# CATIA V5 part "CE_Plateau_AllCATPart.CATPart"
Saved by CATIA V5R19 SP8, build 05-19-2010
Part number: CE3_Plateau_AllCATPart
Bounding box of the stored display mesh (mm): x -297.501 to 295.5, y 20.663 to 1583.163, z -37.994 to 169.547
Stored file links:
  D:\Documents\1_Travail\1 - ac-limoges.fr\ac-limoges.fr\Emmanuel Maynard - STI2D_Turgot\2 -2I2D\1_SEQUENCE_ Tapis_de_course\3- Spécificités\Spé_ITEC\3-Pente\Tapis_TC520B_Pente\CE_Plateau_AllCATPart.CATPart
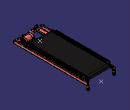
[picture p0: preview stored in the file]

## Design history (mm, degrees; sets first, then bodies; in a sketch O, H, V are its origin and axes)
AxisSystem1: origin (0, 0, 0), X (1, 0, 0), Y (0, 1, 0), Z (0, 0, 1)
Body1 (main body)
  Sketch1 on YZ plane of AxisSystem1, origin (0, 0, 0), H (0, 1, 0), V (0, 0, 1)
    projected circle E1 centre (1555.6634, -10.5) radius 27.5 from edge [face of Solid100 | face of Solid100]
  Sketch2 on yz-plane, origin (0, 0, 0), H (0, 1, 0), V (0, 0, 1)
    point P1 (1555.6634, -10.5)
    reference projected point E1 (1555.6634, -10.5) from axis of face of Solid100
    projected point E2 (98.6634, 148.5) from axis of face of Solid102
    projected point E3 (280.6634, 75.5) from axis of face of Solid103
    coincidence: P1 E1
  Body2 "S/S Roulettes.1\\Vis ISO 7380 Tete bombee a six pans creux M8x40.1"
    Solid1: solid without history
    Body3 "S/S Roulettes.1\\Vis ISO 7380 Tete bombee a six pans creux M8x40.1\\Corps de pièce.2"
      Solid2 "Solide.1": solid without history
    Add1 "S/S Roulettes.1\\Vis ISO 7380 Tete bombee a six pans creux M8x40.1\\Corps de pièce.2": tool Body3
  Add2: tool Body2
  Body4 "S/S Roulettes.1\\ecrou_iso_7040-M8-10.1\\ecrou_iso_7040-m8-10"
    Solid3 "Solide.1": solid without history
  Add3: tool Body4
  Body5 "S/S Roulettes.1\\Vis ISO 7380 Tete bombee a six pans creux M8x40.2"
    Solid4 "Solide.1": solid without history
    Body6 "S/S Roulettes.1\\Vis ISO 7380 Tete bombee a six pans creux M8x40.2\\Corps de pièce.2"
      Solid5 "Solide.1": solid without history
    Add4 "S/S Roulettes.1\\Vis ISO 7380 Tete bombee a six pans creux M8x40.2\\Corps de pièce.2": tool Body6
  Add5: tool Body5
  Body7 "S/S Roulettes.1\\ecrou_iso_7040-M8-10.2\\ecrou_iso_7040-m8-10"
    Solid6 "Solide.1": solid without history
  Add6: tool Body7
  Body8 "S/S Roulettes.1\\Part1.8\\Corps principal"
    Solid7 "Solide.1": solid without history
  Add7: tool Body8
  Body9 "s/s Moteur.1\\ISO 4762 SCREW M8x16 STEEL HEXAGON SOCKET HEAD CAP.4\\PartBody"
    Solid8 "Solide.1": solid without history
  Add8: tool Body9
  Body10 "s/s Moteur.1\\ISO 8738 WASHER 8 STEEL GRADE A PLAIN WASHER FOR CLEVIS PIN.6\\Corps principal"
    Solid9 "Solide.1": solid without history
  Add9: tool Body10
  Body11 "s/s Moteur.1\\ISO 4762 SCREW M8x16 STEEL HEXAGON SOCKET HEAD CAP.3\\PartBody"
    Solid10 "Solide.1": solid without history
  Add10: tool Body11
  Body12 "s/s Moteur.1\\ronw8a2.6\\ronw8a2"
    Solid11 "Solide.1": solid without history
  Add11: tool Body12
  Body13 "s/s Moteur.1\\ronw8a2.5\\ronw8a2"
    Solid12 "Solide.1": solid without history
  Add12: tool Body13
  Body14 "s/s Moteur.1\\ISO 8738 WASHER 8 STEEL GRADE A PLAIN WASHER FOR CLEVIS PIN.5\\Corps principal"
    Solid13 "Solide.1": solid without history
  Add13: tool Body14
  Body15 "s/s Moteur.1\\ISO 4016 BOLT M8x40 STEEL GRADE C HEXAGON HEAD.1\\PartBody"
    Solid14 "Solide.1": solid without history
  Add14: tool Body15
  Body16 "s/s Moteur.1\\ISO 4032 NUT M8 STEEL GRADE A HEXAGON.1\\Corps principal"
    Solid15 "Solide.1": solid without history
  Add15: tool Body16
  Body17 "s/s Moteur.1\\Part1.13\\Corps principal"
    Solid16 "Solide.1": solid without history
  Add16: tool Body17
  Body18 "s/s Moteur.1\\ISO 4762 SCREW M8x16 STEEL HEXAGON SOCKET HEAD CAP.2\\PartBody"
    Solid17 "Solide.1": solid without history
  Add17: tool Body18
  Body19 "s/s Moteur.1\\ISO 4762 SCREW M8x35 STEEL HEXAGON SOCKET HEAD CAP.2\\PartBody"
    Solid18 "Solide.1": solid without history
  Add18: tool Body19
  Body20 "s/s Moteur.1\\ISO 4762 SCREW M8x35 STEEL HEXAGON SOCKET HEAD CAP.1\\PartBody"
    Solid19 "Solide.1": solid without history
  Add19: tool Body20
  Body21 "s/s Moteur.1\\ISO 4762 SCREW M8x16 STEEL HEXAGON SOCKET HEAD CAP.1\\PartBody"
    Solid20 "Solide.1": solid without history
  Add20: tool Body21
  Body22 "s/s Moteur.1\\ronw8a2.4\\ronw8a2"
    Solid21 "Solide.1": solid without history
  Add21: tool Body22
  Body23 "s/s Moteur.1\\ronw8a2.3\\ronw8a2"
    Solid22 "Solide.1": solid without history
  Add22: tool Body23
  Body24 "s/s Moteur.1\\ronw8a2.2\\ronw8a2"
    Solid23 "Solide.1": solid without history
  Add23: tool Body24
  Body25 "s/s Moteur.1\\ronw8a2.1\\ronw8a2"
    Solid24 "Solide.1": solid without history
  Add24: tool Body25
  Body26 "s/s Moteur.1\\ISO 8738 WASHER 8 STEEL GRADE A PLAIN WASHER FOR CLEVIS PIN.4\\Corps principal"
    Solid25 "Solide.1": solid without history
  Add25: tool Body26
  Body27 "s/s Moteur.1\\ISO 8738 WASHER 8 STEEL GRADE A PLAIN WASHER FOR CLEVIS PIN.3\\Corps principal"
    Solid26 "Solide.1": solid without history
  Add26: tool Body27
  Body28 "s/s Moteur.1\\ISO 8738 WASHER 8 STEEL GRADE A PLAIN WASHER FOR CLEVIS PIN.2\\Corps principal"
    Solid27 "Solide.1": solid without history
  Add27: tool Body28
  Body29 "s/s Moteur.1\\ISO 8738 WASHER 8 STEEL GRADE A PLAIN WASHER FOR CLEVIS PIN.1\\Corps principal"
    Solid28 "Solide.1": solid without history
  Add28: tool Body29
  Body30 "s/s Moteur.1\\Part1.12\\Corps principal"
    Solid29 "Solide.1": solid without history
  Add29: tool Body30
  Body31 "s/s plaque.1\\Part1.2"
    Solid30 "Solide.1": solid without history
    Body32 "s/s plaque.1\\Part1.2\\Vis"
      Solid31 "Solide.1": solid without history
    Add30 "s/s plaque.1\\Part1.2\\Vis": tool Body32
    Body33 "s/s plaque.1\\Part1.2\\Corps de pièce.5"
      Solid32 "Solide.1": solid without history
    Add31 "s/s plaque.1\\Part1.2\\Corps de pièce.5": tool Body33
  Add32: tool Body31
  Body34 "s/s plaque.1\\Part1.3"
    Solid33 "Solide.1": solid without history
    Body35 "s/s plaque.1\\Part1.3\\Vis"
      Solid34 "Solide.1": solid without history
    Add33 "s/s plaque.1\\Part1.3\\Vis": tool Body35
    Body36 "s/s plaque.1\\Part1.3\\Corps de pièce.5"
      Solid35 "Solide.1": solid without history
    Add34 "s/s plaque.1\\Part1.3\\Corps de pièce.5": tool Body36
  Add35: tool Body34
  Body37 "s/s plaque.1\\Part1.4"
    Solid36 "Solide.1": solid without history
    Body38 "s/s plaque.1\\Part1.4\\Vis"
      Solid37 "Solide.1": solid without history
    Add36 "s/s plaque.1\\Part1.4\\Vis": tool Body38
    Body39 "s/s plaque.1\\Part1.4\\Corps de pièce.5"
      Solid38 "Solide.1": solid without history
    Add37 "s/s plaque.1\\Part1.4\\Corps de pièce.5": tool Body39
  Add38: tool Body37
  Body40 "s/s plaque.1\\Part1.5"
    Solid39 "Solide.1": solid without history
    Body41 "s/s plaque.1\\Part1.5\\Vis"
      Solid40 "Solide.1": solid without history
    Add39 "s/s plaque.1\\Part1.5\\Vis": tool Body41
    Body42 "s/s plaque.1\\Part1.5\\Corps de pièce.5"
      Solid41 "Solide.1": solid without history
    Add40 "s/s plaque.1\\Part1.5\\Corps de pièce.5": tool Body42
  Add41: tool Body40
  Body43 "s/s plaque.1\\Part1.6"
    Solid42 "Solide.1": solid without history
    Body44 "s/s plaque.1\\Part1.6\\Vis"
      Solid43 "Solide.1": solid without history
    Add42 "s/s plaque.1\\Part1.6\\Vis": tool Body44
    Body45 "s/s plaque.1\\Part1.6\\Corps de pièce.5"
      Solid44 "Solide.1": solid without history
    Add43 "s/s plaque.1\\Part1.6\\Corps de pièce.5": tool Body45
  Add44: tool Body43
  Body46 "s/s plaque.1\\Part1.7"
    Solid45 "Solide.1": solid without history
    Body47 "s/s plaque.1\\Part1.7\\Vis"
      Solid46 "Solide.1": solid without history
    Add45 "s/s plaque.1\\Part1.7\\Vis": tool Body47
    Body48 "s/s plaque.1\\Part1.7\\Corps de pièce.5"
      Solid47 "Solide.1": solid without history
    Add46 "s/s plaque.1\\Part1.7\\Corps de pièce.5": tool Body48
  Add47: tool Body46
  Body49 "s/s plaque.1\\Part1.1\\Corps principal"
    Solid48 "Solide.1": solid without history
  Add48: tool Body49
  Body50 "s/s plaque.1\\ISO 7046-1 SCREW M6x25-H STEEL GRADE A COUNTERSUNK FLAT HEAD.1\\PartBody"
    Solid49 "Solide.1": solid without history
  Add49: tool Body50
  Body51 "s/s plaque.1\\ISO 7046-1 SCREW M6x25-H STEEL GRADE A COUNTERSUNK FLAT HEAD.2\\PartBody"
    Solid50 "Solide.1": solid without history
  Add50: tool Body51
  Body52 "s/s plaque.1\\ISO 7046-1 SCREW M6x25-H STEEL GRADE A COUNTERSUNK FLAT HEAD.3\\PartBody"
    Solid51 "Solide.1": solid without history
  Add51: tool Body52
  Body53 "s/s plaque.1\\ISO 7046-1 SCREW M6x25-H STEEL GRADE A COUNTERSUNK FLAT HEAD.4\\PartBody"
    Solid52 "Solide.1": solid without history
  Add52: tool Body53
  Body54 "s/s plaque.1\\ISO 7046-1 SCREW M6x25-H STEEL GRADE A COUNTERSUNK FLAT HEAD.5\\PartBody"
    Solid53 "Solide.1": solid without history
  Add53: tool Body54
  Body55 "s/s plaque.1\\ISO 7046-1 SCREW M6x25-H STEEL GRADE A COUNTERSUNK FLAT HEAD.6\\PartBody"
    Solid54 "Solide.1": solid without history
  Add54: tool Body55
  Body56 "s/s plaque.1\\ISO 7046-1 SCREW M6x25-H STEEL GRADE A COUNTERSUNK FLAT HEAD.7\\PartBody"
    Solid55 "Solide.1": solid without history
  Add55: tool Body56
  Body57 "s/s plaque.1\\ISO 7046-1 SCREW M6x25-H STEEL GRADE A COUNTERSUNK FLAT HEAD.8\\PartBody"
    Solid56 "Solide.1": solid without history
  Add56: tool Body57
  Body58 "s/s plaque.1\\Part1.9\\Corps principal"
    Solid57 "Solide.1": solid without history
  Add57: tool Body58
  Body59 "s/s plaque.1\\Part1.11\\Corps principal"
    Solid58 "Solide.1": solid without history
  Add58: tool Body59
  Body60 "s/s plaque.1\\Part1.10\\Corps principal"
    Solid59 "Solide.1": solid without history
  Add59: tool Body60
  Body61 "s/s plaque.1\\Part1.12\\Corps principal"
    Solid60 "Solide.1": solid without history
  Add60: tool Body61
  Body62 "s/s plaque.1\\Part1.13\\Corps principal"
    Solid61 "Solide.1": solid without history
  Add61: tool Body62
  Body63 "s/s plaque.1\\Part1.14\\Corps principal"
    Solid62 "Solide.1": solid without history
  Add62: tool Body63
  Body64 "s/s plaque.1\\Part1.15\\Corps principal"
    Solid63 "Solide.1": solid without history
  Add63: tool Body64
  Body65 "s/s plaque.1\\Part1.16\\Corps principal"
    Solid64 "Solide.1": solid without history
  Add64: tool Body65
  Body66 "s/s plaque.1\\Protection tapis.1\\Corps principal"
    Solid65 "Solide.1": solid without history
  Add65: tool Body66
  Body67 "s/s plaque.1\\Protection tapis.2\\Corps principal"
    Solid66 "Solide.1": solid without history
  Add66: tool Body67
  Body68 "s/s Axe_Tambour moteur.1\\Axe tambour moteur\\Corps principal"
    Solid67 "Solide.1": solid without history
  Add67: tool Body68
  Body69 "s/s Axe_Tambour moteur.1\\JIS B 2804 RING 15 STEEL RETAINING FOR ON SHAFT USE TYPE CE.1\\Corps principal"
    Solid68 "Solide.1": solid without history
  Add68: tool Body69
  Body70 "s/s Axe_Tambour moteur.1\\JIS B 2804 RING 15 STEEL RETAINING FOR ON SHAFT USE TYPE CE.2\\Corps principal"
    Solid69 "Solide.1": solid without history
  Add69: tool Body70
  Body71 "s/s Tambour_Tendeur.1\\Axe tambour tendeur.1\\Corps principal"
    Solid70 "Solide.1": solid without history
  Add70: tool Body71
  Body72 "Product1.6\\Rondelle plastique M12.1\\Corps principal"
    Solid71 "Solide.1": solid without history
  Add71: tool Body72
  Body73 "Product1.6\\Vis Epaulée Tetebombee a six pan creux M10x26-11.1\\screw_gb_t_70_2_m10x25"
    Solid72 "Solide.1": solid without history
  Add72: tool Body73
  Body74 "Product1.6\\Rondelle plastique M12.2\\Corps principal"
    Solid73 "Solide.1": solid without history
  Add73: tool Body74
  Body75 "Product1.6\\ecrou_iso_7040-m10-10.1\\ecrou_iso_7040-m10-10"
    Solid74 "Solide.1": solid without history
  Add74: tool Body75
  Body76 "Product1.6\\ecrou_iso_7040-m10-10.2\\ecrou_iso_7040-m10-10"
    Solid75 "Solide.1": solid without history
  Add75: tool Body76
  Body77 "Product1.6\\Rondelle plastique M12.3\\Corps principal"
    Solid76 "Solide.1": solid without history
  Add76: tool Body77
  Body78 "Product1.6\\Rondelle plastique M12.4\\Corps principal"
    Solid77 "Solide.1": solid without history
  Add77: tool Body78
  Body79 "Product1.6\\Vis Epaulée Tetebombee a six pan creux M10x26-11.2\\screw_gb_t_70_2_m10x25"
    Solid78 "Solide.1": solid without history
  Add78: tool Body79
  Body80 "Product1.6\\Bouchon-Plateau.10\\Corps principal"
    Solid79 "Solide.1": solid without history
  Add79: tool Body80
  Body81 "Product1.6\\Bouchon-Plateau.11\\Corps principal"
    Solid80 "Solide.1": solid without history
  Add80: tool Body81
  Body82 "Product1.6\\ISO 4762 SCREW M8x80 STEEL HEXAGON SOCKET HEAD CAP.1\\PartBody"
    Solid81 "Solide.1": solid without history
  Add81: tool Body82
  Body83 "Product1.6\\ISO 4762 SCREW M8x80 STEEL HEXAGON SOCKET HEAD CAP.2\\PartBody"
    Solid82 "Solide.1": solid without history
  Add82: tool Body83
  Body84 "Product1.6\\ISO 4762 SCREW M8x80 STEEL HEXAGON SOCKET HEAD CAP.3\\PartBody"
    Solid83 "Solide.1": solid without history
  Add83: tool Body84
  Body85 "Product1.6\\ISO 7089 WASHER 8x16 STEEL GRADE A PLAIN NORMAL SERIES.1\\PartBody"
    Solid84 "Solide.1": solid without history
  Add84: tool Body85
  Body86 "Product1.6\\ISO 7089 WASHER 8x16 STEEL GRADE A PLAIN NORMAL SERIES.2\\PartBody"
    Solid85 "Solide.1": solid without history
  Add85: tool Body86
  Body87 "Product1.6\\ISO 7089 WASHER 8x16 STEEL GRADE A PLAIN NORMAL SERIES.3\\PartBody"
    Solid86 "Solide.1": solid without history
  Add86: tool Body87
  Body88 "ISO 7089 WASHER 10x20 STEEL GRADE A PLAIN NORMAL SERIES.1\\PartBody"
    Solid87 "Solide.1": solid without history
  Add87: tool Body88
  Body89 "ecrou_iso_7040-m10-10.3\\ecrou_iso_7040-m10-10"
    Solid88 "Solide.1": solid without history
  Add88: tool Body89
  Body90 "Courroie.1\\Corps principal"
    Solid89 "Solide.1": solid without history
  Add89: tool Body90
  Body91 "Tapis.1\\Corps principal"
    Solid90 "Solide.1": solid without history
  Add90: tool Body91
  Body92 "Product1.6\\Cadre Plateau.1\\Corps de pièce.11"
    Solid91 "Solide.1": solid without history
  Add91: tool Body92
  Body93 "Product1.6\\Cadre Plateau.1\\Corps de pièce.10"
    Solid92 "Solide.1": solid without history
  Add92: tool Body93
  Body94 "Product1.6\\Cadre Plateau.1\\Corps de pièce.9"
    Solid93 "Solide.1": solid without history
  Add93: tool Body94
  Body95 "Product1.6\\Cadre Plateau.1\\Corps de pièce.8"
    Solid94 "Solide.1": solid without history
  Add94: tool Body95
  Body96 "Product1.6\\Cadre Plateau.1\\Corps de pièce.6"
    Solid95 "Solide.1": solid without history
  Add95: tool Body96
  Body97 "Product1.6\\Cadre Plateau.1\\Corps de pièce.5"
    Solid96 "Solide.1": solid without history
  Add96: tool Body97
  Body98 "Product1.6\\Cadre Plateau.1\\Corps de pièce.4"
    Solid97 "Solide.1": solid without history
  Add97: tool Body98
  Body99 "Product1.6\\Cadre Plateau.1\\Corps de pièce.3"
    Solid98 "Solide.1": solid without history
  Add98: tool Body99
  Body100 "Product1.6\\Cadre Plateau.1\\Corps de pièce.2"
    Solid99 "Solide.1": solid without history
  Add99: tool Body100
Body101 "S/S Roulettes.1\\Part1.9\\Corps principal"
  Solid100 "Solide.1": solid without history
Body102 "Product1.6\\Cadre Plateau.1"
  Solid101 "Solide.1": solid without history
Body103 "ISO 4014 BOLT M10x50 STEEL GRADE A HEXAGON HEAD.1\\PartBody"
  Solid102 "Solide.1": solid without history
Body104 "Product1.6\\Cadre Plateau.1\\Corps de pièce.7"
  Solid103 "Solide.1": solid without history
